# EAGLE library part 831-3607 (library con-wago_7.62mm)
Serie 831, Stiftleiste (für Leiterplatten) mit geraden Einlötstiften / Series 831, Male header (for PCBs) with straight solder pins Polzahl / Pole No.: 7 Bemessungsspannung / Rated Voltage: 630 V Nennstrom / Nominal Current: 41 A Lötstiftlänge: / Solder Pin Length: 4 mm Farbe / Color: lichtgrau / light gray Stand: 01.01.2012. Die jeweils aktuellen Daten zu diesem Artikel finden Sie in unserem Produktkatalog, den Sie unter www.wago.com einsehen können. As of: 01/01/2012. Please find the newest data for this article in our product catalogue, which can be viewed under www.wago.com.
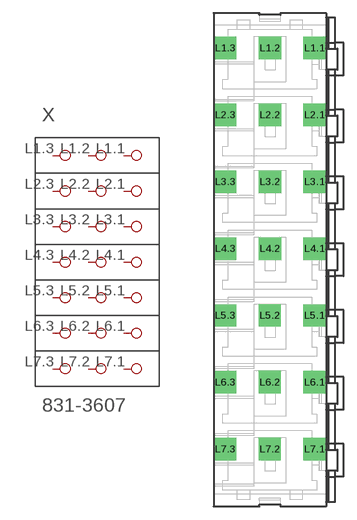
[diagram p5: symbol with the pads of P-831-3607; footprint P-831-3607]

Designator prefix X

## 831-3607  [P-831-3607]
L1.1  P1.1
L1.2  P1.2
L1.3  P1.3
L2.1  P2.1
L2.2  P2.2
L2.3  P2.3
L3.1  P3.1
L3.2  P3.2
L3.3  P3.3
L4.1  P4.1
L4.2  P4.2
L4.3  P4.3
L5.1  P5.1
L5.2  P5.2
L5.3  P5.3
L6.1  P6.1
L6.2  P6.2
L6.3  P6.3
L7.1  P7.1
L7.2  P7.2
L7.3  P7.3

## Footprint P-831-3607 (pad centres in mm)
drill 1.7 square: L1.1 4.08,24.13; L1.2 -1,24.13; L1.3 -6.08,24.13; L2.1 4.08,16.51; L2.2 -1,16.51; L2.3 -6.08,16.51; L3.1 4.08,8.89; L3.2 -1,8.89; L3.3 -6.08,8.89; L4.1 4.08,1.27; L4.2 -1,1.27; L4.3 -6.08,1.27; L5.1 4.07,-6.35; L5.2 -1.01,-6.35; L5.3 -6.09,-6.35; L6.1 4.07,-13.97; L6.2 -1.01,-13.97; L6.3 -6.09,-13.97; L7.1 4.07,-21.59; L7.2 -1.01,-21.59; L7.3 -6.09,-21.59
